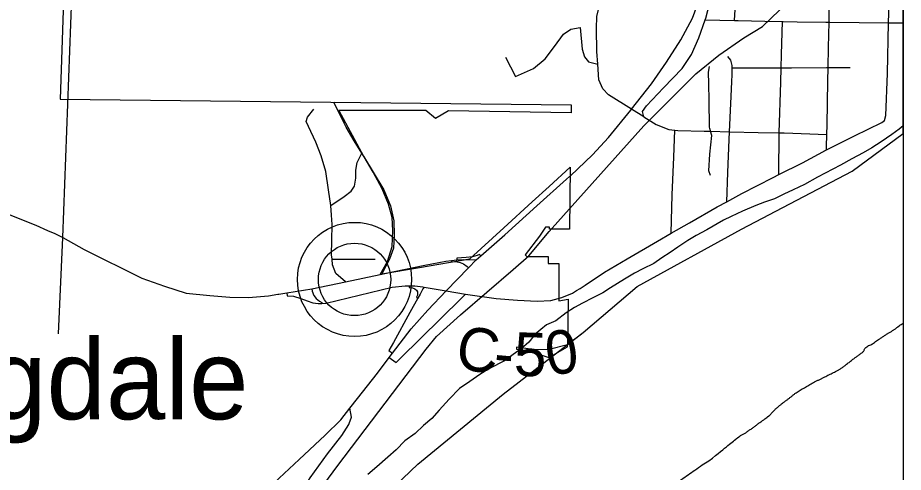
# Model space of a CAD drawing. Extents: x -84548 to 2262448, y -162180 to 525962.
# Drawn here: x 106892 to 112989, y 156669 to 159796 of the extents above; entities that cross this region are included whole.
import ezdxf

# ---------------------------------------------------------------- set-up
doc = ezdxf.new("R2010")
doc.units = 0
for name, color, linetype in [('GM_X_Adjacent_County_Text', 7, 'Continuous'), ('GM_X_County', 7, 'Continuous'), ('GM_X_County_Road', 7, 'Continuous'), ('GM_X_Hydro', 7, 'Continuous'), ('GM_X_Hydro_Text', 7, 'Continuous'), ('GM_X_Interstate_Location', 7, 'Continuous'), ('GM_X_Major_Lake_Text', 7, 'Continuous'), ('GM_X_Major_River', 7, 'Continuous'), ('GM_X_Minor_Lake', 7, 'Continuous'), ('GM_X_Minor_River_Text', 7, 'Continuous'), ('GM_X_Township_ROW', 7, 'Continuous'), ('GM_X_Township_Subdivision_Text', 7, 'Continuous'), ('GM_X_Unincorporated_Location', 7, 'Continuous'), ('GM_X_US_Location', 7, 'Continuous')]:
    doc.layers.add(name, color=color, linetype=linetype)

msp = doc.modelspace()

# ---------------------------------------------------------------- linework, layer by layer
at = {"layer": 'GM_X_County'}
msp.add_line((112988.6, 170685.8), (112988.6, 134781.8), dxfattribs=at)
at = {"layer": 'GM_X_Hydro'}
for p, q in [((107203.1, 158285.3), (107630.7, 169939.1)), ((112635.5, 158740.2), (112988.6, 158999.4)), ((111874.1, 158341.2), (112635.5, 158740.2)), ((111156.7, 157947.1), (111874.1, 158341.2)), ((107171.7, 157620.4), (107203.1, 158285.3)), ((110785.2, 157631.3), (111156.7, 157947.1)), ((110234.9, 157206), (110785.2, 157631.3)), ((109647.6, 156723.8), (110234.9, 157206)), ((109061.6, 156171.4), (109647.6, 156723.8))]:
    msp.add_line(p, q, dxfattribs=at)
at = {"layer": 'GM_X_Hydro_Text'}
for points in [[(110080.3, 158158.9), (110071.2, 158167.6), (110055.4, 158160.2), (110022.3, 158152.3), (109980.4, 158147.3), (109914.6, 158141.9), (109915.4, 158130.4)], [(109879.1, 158127), (109879.4, 158120.2), (109916.6, 158116.8), (109937.3, 158111.6), (109960.5, 158102.2), (109986.3, 158085.7), (109995.8, 158076.3)], [(108744.6, 157903.1), (108747.9, 157881.9), (108790.6, 157879.5), (108841.9, 157865.4), (108883.6, 157848), (108924.3, 157835.7), (108961.1, 157830.2), (108986.6, 157831), (109015.6, 157832), (109469, 157943), (109559.8, 157951.6), (109586.2, 157951.7), (109625.6, 157951.9), (109682, 157944.3), (109689.9, 157943.3)], [(108917.3, 157931.6), (108920.1, 157915.2), (108931, 157885.5), (108946.7, 157864.3), (108969.2, 157847.1), (108986.4, 157837.7), (108986.6, 157831)], [(109689.9, 157943.3), (109681.3, 157930.4), (109662.4, 157894.3), (109646.9, 157866.7), (109591.5, 157768), (109479.5, 157562.2), (109447, 157505.9), (109471.5, 157487.8)], [(109586.2, 157951.7), (109586.2, 157939.2), (109610.1, 157937.1), (109624.8, 157931.6), (109637.9, 157921.2), (109643.4, 157909.3), (109644.9, 157899.5), (109644.5, 157888.5), (109638.2, 157873.1), (109646.9, 157866.7)], [(109449.9, 157458.6), (109497.4, 157423.4), (109527.4, 157454.2), (109944.6, 157864.4), (109974.9, 157895.2)]]:
    msp.add_lwpolyline(points, dxfattribs=at)
at = {"layer": 'GM_X_Interstate_Location'}
for points in [[(112988.6, 159051.8), (112961.3, 159030.1), (112909.9, 158993.2), (112836.6, 158941.9), (112771.2, 158900.7), (112711.6, 158867.7), (112634.2, 158826.3), (112556.8, 158782.9), (112397.9, 158700.1), (112308.6, 158648.5), (112231.1, 158613.2), (112165.5, 158582), (112101.9, 158550.9), (112032.2, 158527.7), (111972.5, 158504.7), (111881.1, 158465.1), (111803.5, 158429.8), (111751.9, 158402.8), (111636.8, 158336.8), (111563.4, 158297.5), (111505.8, 158262.5), (111436.5, 158217.2), (111383, 158180.2), (111325.5, 158145.2), (111272.1, 158106.2), (111194.6, 158068.9), (111139, 158037.9), (111069.6, 157996.7), (110972.4, 157936.9), (110920.9, 157904), (110851.3, 157868.8), (110779.9, 157831.5), (110724.3, 157802.5)], [(110724.3, 157802.5), (110666.8, 157765.5), (110597.6, 157710.2), (110531.9, 157683.1), (110454.8, 157619.6), (110411.7, 157564.8), (110358.4, 157517.8), (110302.9, 157478.8), (110247.5, 157437.7), (110136.3, 157379.8), (110072.8, 157342.6), (110003.5, 157293.4), (109934.2, 157246.1), (109863.3, 157170.8), (109792.4, 157095.4), (109743.3, 157038.4), (109686, 156991.3), (109628.8, 156936.3), (109557.5, 156885), (109498.4, 156823.8), (109439.1, 156772.7), (109364.1, 156705.3), (109302.9, 156654.2)]]:
    msp.add_lwpolyline(points, dxfattribs=at)
msp.add_open_spline([(111650.3, 156747.1), (111718.8, 156802.3), (111787.2, 156857.5), (111855.7, 156912.7), (111871.3, 156925.3), (111891.3, 156931.4), (111907.6, 156943.1), (111926.2, 156956.5), (111944.9, 156969.9), (111963.4, 156983.5), (111982.7, 156997.6), (112002, 157011.8), (112021.3, 157025.9), (112034.7, 157035.8), (112048.1, 157045.8), (112061.1, 157056.2), (112080.8, 157071.8), (112096, 157092.2), (112114.9, 157108.7), (112129.2, 157121.1), (112143.7, 157133.4), (112158.8, 157145), (112173.9, 157156.7), (112189.4, 157167.8), (112204.6, 157179.4), (112220.1, 157191.2), (112234.6, 157204.3), (112250.5, 157215.7), (112263.9, 157225.4), (112278.1, 157233.7), (112292.4, 157242), (112307.6, 157250.9), (112322.9, 157259.7), (112338.3, 157268.4), (112354.2, 157277.3), (112370, 157286.3), (112386.2, 157294.7), (112404, 157303.9), (112422.3, 157312.1), (112440.1, 157321.1), (112454.8, 157328.4), (112469.4, 157336), (112484.1, 157343.4), (112499.3, 157351.1), (112514.9, 157357.8), (112530, 157365.7), (112548.5, 157375.3), (112565.3, 157387.6), (112581.9, 157400.1), (112604.1, 157416.7), (112625.7, 157433.9), (112647.7, 157450.6), (112666, 157464.5), (112685.2, 157477.2), (112703.5, 157491), (112718, 157501.8), (112722.7, 157522.8), (112737.3, 157533.3), (112749.5, 157542), (112765, 157545.1), (112777.3, 157553.6), (112790.7, 157562.8), (112803.6, 157572.9), (112817.2, 157581.9), (112835.7, 157594.2), (112854.3, 157606.3), (112873, 157618.3), (112889.5, 157628.8), (112906.5, 157638.2), (112922.9, 157648.7), (112938.3, 157658.4), (112951.7, 157671), (112966.8, 157681), (112973.9, 157685.7), (112981.2, 157689.9), (112988.6, 157694.1)], degree=3, dxfattribs=at)
msp.add_spline([(110828.8, 156116.7), (110868.7, 156149), (110912.5, 156185.4), (110962.4, 156227.8), (111004.2, 156266.1), (111048.1, 156302.5), (111095.9, 156340.9), (111149.7, 156385.3), (111191.6, 156419.6), (111231.5, 156449.9), (111275.3, 156484.3), (111337.1, 156532.7), (111381, 156563.1), (111460.8, 156619.7), (111506.7, 156652), (111554.6, 156684.4), (111604.4, 156720.8), (111650.3, 156747.1)], degree=3, dxfattribs=at)
at = {"layer": 'GM_X_Major_Lake_Text'}
for points in [[(110691.6, 158704.5), (110696.5, 158709), (110849.2, 158852.2), (110960.3, 158971.2), (111113, 159160.7), (111118, 159167), (111255.6, 159342), (111358.5, 159491), (111457.4, 159644), (111536.3, 159792.8), (111604.8, 159977.6), (111653.5, 160150.2), (111683.1, 160332.9), (111685.9, 160350.7), (111700.2, 160577.2), (111700.6, 160614), (111702.5, 160789.5), (111687.1, 160961.6), (111659.4, 161171.7), (111644.1, 161329.8), (111643.8, 161343), (111642, 161417.1), (111641.2, 161450), (111646.5, 161506.4)], [(105332.3, 158775.1), (105386.5, 158769.4), (105485.8, 158759), (105680.1, 158740.5), (105822.4, 158719.6), (105849.6, 158715), (105982.7, 158692.8), (106169.2, 158646.1), (106349.6, 158619.2), (106575.7, 158543.8), (107016.3, 158369.9), (107096.9, 158333.4)], [(110048.3, 158131), (110080.3, 158158.9), (110245.1, 158302.8), (110465.7, 158502.8), (110670.4, 158684.6), (110691.6, 158704.5)], [(107096.9, 158333.4), (107146.7, 158310.9)], [(107146.7, 158310.9), (107203.1, 158285.3), (107349.6, 158201.8), (107746.7, 158004.7), (107903.2, 157949.7), (108052.6, 157901.5), (108214.9, 157884.7), (108353.1, 157873.7), (108481.2, 157870.7), (108619.2, 157883.8), (108683.5, 157893.7), (108690.7, 157894.8)], [(108690.7, 157894.8), (108744.6, 157903.1), (108917.3, 157931.6), (109149.4, 157979.4), (109386.6, 158029.9), (109484.5, 158050.6), (109694.3, 158094.3), (109840.1, 158121.2), (109879.1, 158127), (109915.4, 158130.4), (109960.6, 158132.1), (110048.3, 158131)], [(109841.3, 157917.9), (109995.8, 158076.3), (110048.3, 158131)], [(109471.5, 157487.8), (109601.8, 157656.9), (109714.8, 157784), (109841.3, 157917.9)], [(109689.9, 157943.3), (109841.3, 157917.9), (109974.9, 157895.2)], [(107008.9, 154153.6), (107163.6, 154427.6), (107218.5, 154576.2), (107271.6, 154686.8), (107362.6, 154825.7), (107481.2, 155004.9), (107629.6, 155222.3), (107786, 155445.8), (107922.4, 155651.2), (108072.8, 155876.7), (108229, 156106.2), (108357.7, 156285.4), (108453, 156386.3), (108556.2, 156497.3), (108691.3, 156628.5), (108830.3, 156757.7), (109009.1, 156925.3), (109116.4, 157030.3), (109177.8, 157108.9), (109231.3, 157177.4), (109370, 157350.7), (109449.9, 157458.6), (109471.5, 157487.8)]]:
    msp.add_lwpolyline(points, dxfattribs=at)
at = {"layer": 'GM_X_Major_River'}
for radius in [392.8, 249]:
    msp.add_circle((109211, 157995.6), radius, dxfattribs=at)
at = {"layer": 'GM_X_Minor_Lake'}
for points in [[(109174.2, 157004.8), (109189.3, 157047.5), (109177.8, 157108.9)], [(108891.9, 156611.3), (108893.1, 156613), (108905.7, 156631), (109024.8, 156796), (109124.1, 156920.9), (109171.6, 156997.3), (109173.6, 157002.9), (109174.2, 157004.8)]]:
    msp.add_lwpolyline(points, dxfattribs=at)
at = {"layer": 'GM_X_Minor_River_Text'}
msp.add_lwpolyline([(109974.9, 157895.2), (110186.8, 157864.9), (110333.2, 157854), (110467.4, 157846.8), (110561.3, 157850.8), (110638.9, 157872.5), (110710.3, 157902.1), (110739.4, 157919.7)], dxfattribs=at)
at = {"layer": 'GM_X_Township_ROW'}
for points in [[(109153.6, 159044.5), (109138.5, 159070.6), (109067.5, 159215.7)], [(109046.6, 158505), (109031.8, 158613.1), (109012.8, 158739.2), (108982, 158847.2), (108945.3, 158941.1), (108894.6, 159047), (108878.3, 159082.9), (108888.1, 159113.1), (108931.7, 159167.4)], [(109386.6, 158029.9), (109437.5, 158118.8), (109468.8, 158223.2), (109474, 158331.4), (109469.3, 158421.6), (109444.6, 158513.6), (109401.9, 158619.5), (109339, 158733.3), (109276.2, 158839.1), (109261, 158864), (109209.4, 158948.8), (109153.8, 159044.3), (109153.6, 159044.5)], [(109149.4, 157979.4), (109082, 158036.3), (109059.5, 158096.3), (109055.9, 158134.2), (109053, 158164.4), (109054.3, 158262.6), (109057.5, 158374.8), (109051.1, 158436.9), (109046.6, 158505), (109140.1, 158565.7), (109187.9, 158602.1), (109209.6, 158638.3), (109219.3, 158692.4), (109218.9, 158746.5), (109228.5, 158800.7), (109261, 158864)], [(109055.9, 158134.2), (109353.4, 158136.3)]]:
    msp.add_lwpolyline(points, dxfattribs=at)
at = {"layer": 'GM_X_Township_Subdivision_Text'}
msp.add_lwpolyline([(107316.7, 163176.9), (107184, 159236.8), (110703, 159197.4), (110702.1, 159142.3), (109858.4, 159156.4), (109767.8, 159104.1), (109702.7, 159158.7), (109102.7, 159158.7), (109273.6, 158844.5), (109412.4, 158611.2), (109457.9, 158502.7), (109481.3, 158398.3), (109484.7, 158302.1), (109478.2, 158209.9), (109451.8, 158135.9), (109398.2, 158033.7), (109658.4, 158078.5), (110003.8, 158138), (110238.3, 158351.1), (110433.7, 158528.8), (110550.9, 158635.3), (110696.3, 158767.5), (110689.7, 158341.9), (110552.3, 158341.9), (110552.3, 158355.4), (110525.3, 158355.4), (110483.9, 158293.9), (110386.4, 158164.6), (110395.8, 158153.4), (110544.9, 158153.4), (110544.9, 158105.4), (110617.3, 158105.4), (110617.4, 157848.6), (110682.2, 157860.1), (110677.3, 157546.2), (110551.1, 157514), (110454.2, 157511), (110326.4, 157528.9), (110325.6, 157517), (110403.8, 157506), (110548.4, 157459), (110676.6, 157533), (110679.3, 157549.5), (110785.2, 157631.3), (111156.7, 157947.1), (111874.1, 158341.2), (112635.5, 158740.2), (112988.6, 158999.4), (112988.6, 170264)], dxfattribs=at)
at = {"layer": 'GM_X_Unincorporated_Location'}
for points in [[(111891.4, 159657.8), (112018.9, 159736.1), (112135.4, 159848.5), (112200.9, 159974.1), (112209.8, 160028.5), (112257.8, 161690.8), (112225.7, 161771), (112101.6, 162053.8), (112048.3, 162219), (111997.4, 162396), (111955.1, 162497.8), (111882.1, 162569.4), (110937.1, 163496.8), (110070.7, 164304.2)], [(108460.4, 155853.3), (109096, 156714.8), (109704.3, 157516.1), (109774.1, 157604.1), (109939.8, 157752.6), (110303.6, 158064.9), (110411.1, 158157.2), (110551.6, 158325.7), (111202.8, 159051.9), (111561.5, 159409.3), (111718, 159537.8), (111891.4, 159657.8)]]:
    msp.add_lwpolyline(points, dxfattribs=at)
at = {"layer": 'GM_X_US_Location'}
for points in [[(111202.7, 159114.2), (111118, 159167), (110958.9, 159266.2), (110920.4, 159307.9), (110891.8, 159369.7), (110885.1, 159477.6), (110879.8, 159564), (110876.1, 159722.3), (110879.3, 159804.5), (110904.2, 159908.9), (110966.1, 160118), (111016.4, 160284.8), (111047.1, 160419.4), (111075.5, 160571.9), (111086.2, 160702.3), (111090.7, 160840.6), (111079.5, 160958.8), (111060.3, 161070.8), (111018.9, 161202.7), (110961.5, 161336.4), (110912.7, 161414)], [(112459.8, 158890.9), (112460.3, 158907.6), (112462.4, 158994), (112464, 159059), (112469.5, 159359.6), (112471.5, 159453.3), (112474.4, 159592.1), (112477.2, 159765.6), (112477.8, 159806.5), (112482.5, 160051), (112483.5, 160096.5), (112487.6, 160277.5), (112487.5, 160455.2), (112487.5, 160467.8), (112497.9, 160816.5), (112506.6, 161153.2), (112534.9, 161152.5)], [(112858.4, 159090.3), (112868.1, 159124.5), (112879.1, 159413.1), (112887.6, 159762.1), (112896.7, 160034.6), (112904.4, 160255.1), (112911.7, 160442.6), (112915.5, 160537.7), (112925.9, 160880.5), (112988.6, 161008.9)], [(111202.7, 159114.2), (111194.3, 159152.2), (111219.9, 159190.6), (111338.7, 159314), (111465.5, 159447.5), (111530.5, 159544.3), (111581.4, 159657), (111625.6, 159781.2), (111630, 159793.8), (111672.3, 159962.5), (111712.8, 160111.2)], [(111826.3, 159778.3), (111846.9, 160112.5)], [(111625.6, 159781.2), (111826.3, 159778.3), (111838.1, 159778.1)], [(111838.1, 159778.1), (111841.6, 159778.1), (111852.4, 159777.9), (112034.6, 159771.7), (112156.7, 159769.5)], [(112132.3, 158717.2), (112134.6, 159003.8), (112145.1, 159351.9), (112148.2, 159450.9), (112151.1, 159544.3), (112156.7, 159769.5)], [(112156.7, 159769.5), (112161.6, 159769.5), (112256.9, 159767.8), (112455.1, 159765.7), (112477.2, 159765.6), (112478.9, 159765.5)], [(112478.9, 159765.5), (112481.8, 159765.5), (112685.3, 159764), (112887.6, 159762.1), (112895.5, 159762), (112908.4, 159761.8)], [(112908.4, 159761.8), (112911.4, 159761.8), (112988.6, 159760.8)], [(110249.6, 159525.8), (110319, 159392.2), (110442.6, 159447.5), (110524, 159514.4), (110587.1, 159599.2), (110650.3, 159684), (110700, 159716.5), (110763.9, 159729.2), (110777.5, 159581), (110794.1, 159527.1), (110822.4, 159493.3), (110885.1, 159477.6)], [(111808.5, 159358.8), (111810.3, 159400.7), (111811.3, 159450.9), (111811.6, 159466.9), (111801.2, 159504.9), (111780.9, 159530.7)], [(111658, 159031.1), (111657.9, 159031.5), (111653.8, 159046.5), (111651.9, 159226.8), (111650.7, 159341.1), (111647.9, 159421.2), (111653.5, 159461.3)], [(111811.3, 159450.9), (112027.9, 159450.9), (112148.2, 159450.9), (112220.1, 159450.8), (112460.3, 159453.2), (112471.5, 159453.3), (112622.4, 159454.7)], [(111774.6, 158530.1), (111781.2, 158731.1), (111788.8, 158959.6), (111791.7, 159011.9), (111802.3, 159206.3), (111808.4, 159355.5), (111808.5, 159358.8)], [(111202.7, 159114.2), (111287.3, 159060.9), (111373.7, 159027.7), (111416.4, 159022.6), (111435.9, 159020.3), (111437.1, 159020.3)], [(112421.8, 158866.6), (112459.7, 158886.7), (112653.3, 158984.1), (112840.5, 159076.1), (112858.4, 159090.3)], [(111390.8, 158313.4), (111398.4, 158577.1), (111409.7, 158837.7), (111416.4, 159022.6)], [(111437.1, 159020.3), (111618.1, 159016.1), (111662.5, 159015), (111791.7, 159011.9), (111794.3, 159011.8), (111990.5, 159005.7), (112134.6, 159003.8), (112168.7, 159003.4), (112462.4, 158994)], [(111661.3, 158711.9), (111650.9, 158743.8), (111657.7, 158858.1), (111670.4, 158986.5), (111662.5, 159015), (111658, 159031.1)], [(110739.4, 157919.7), (110763.6, 157934.4), (110799.2, 157956), (110931.3, 158045), (111087.3, 158138.4), (111296.8, 158259.1), (111390.8, 158313.4), (111516.2, 158385.9), (111707.9, 158494.1), (111774.6, 158530.1), (111878, 158585.9), (112091.7, 158696.6), (112132.3, 158717.2), (112293.6, 158799), (112459.7, 158886.7), (112459.8, 158890.9)]]:
    msp.add_lwpolyline(points, dxfattribs=at)

# ---------------------------------------------------------------- texts
at = {"layer": 'GM_X_Adjacent_County_Text'}
msp.add_text('Springdale', height=550, rotation=0.00001, dxfattribs=at).set_placement((104964.5, 157033.4))
at = {"layer": 'GM_X_County_Road'}
for s, rotation, p in [('C', 350.75263, (109895.4, 157387.3)), ('0', 8.65448, (110548, 157331.8)), ('5', 358.53837, (110305.6, 157332.8)), ('-', 355.00112, (110162.7, 157344.7))]:
    msp.add_text(s, height=300, rotation=rotation, dxfattribs=at).set_placement(p)

doc.saveas('drawing.dxf')
